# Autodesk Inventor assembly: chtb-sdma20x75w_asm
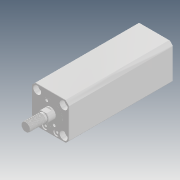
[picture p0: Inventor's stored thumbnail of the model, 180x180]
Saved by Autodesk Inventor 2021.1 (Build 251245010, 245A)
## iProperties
Company: Microsoft
Created: 2018-05
Part Number: chtb-sdma20x75w_asm
Description: STEP AP214
Document SubType Name: Assembly
Designer: user
Title: chtb-sdma20x75w_asm.STEP
Author: Windows
Revision Number: ÈÎºÎ
Sending System: SolidWorks 2015
Preprocessor: SwSTEP 2.0
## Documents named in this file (4)
- D:\Vault_2016\Projekty\Clamptek\Hydraulic\CHTB\CHTB-20\Inventor\CHTB-SDMA20x75W\chtb-sdma20x75w_asm.iam
- D:\Vault_2016\Projekty\Clamptek\Hydraulic\CHTB\CHTB-20\Inventor\CHTB-SDMA20x75W\CHTB-SDMA20X75NBT.ipt
- D:\Vault_2016\Projekty\Clamptek\Hydraulic\CHTB\CHTB-20\Inventor\CHTB-SDMA20x75W\CHTB-SDMA20X75WHSG.ipt
- D:\Vault_2016\Projekty\Clamptek\Hydraulic\CHTB\CHTB-20\Inventor\CHTB-SDMA20x75W\QG_3.ipt
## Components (3 placed, 3 different names)
1. CHTB-SDMA20X75NBT_1
2. CHTB-SDMA20X75WHSG_2
3. QG_3_3
